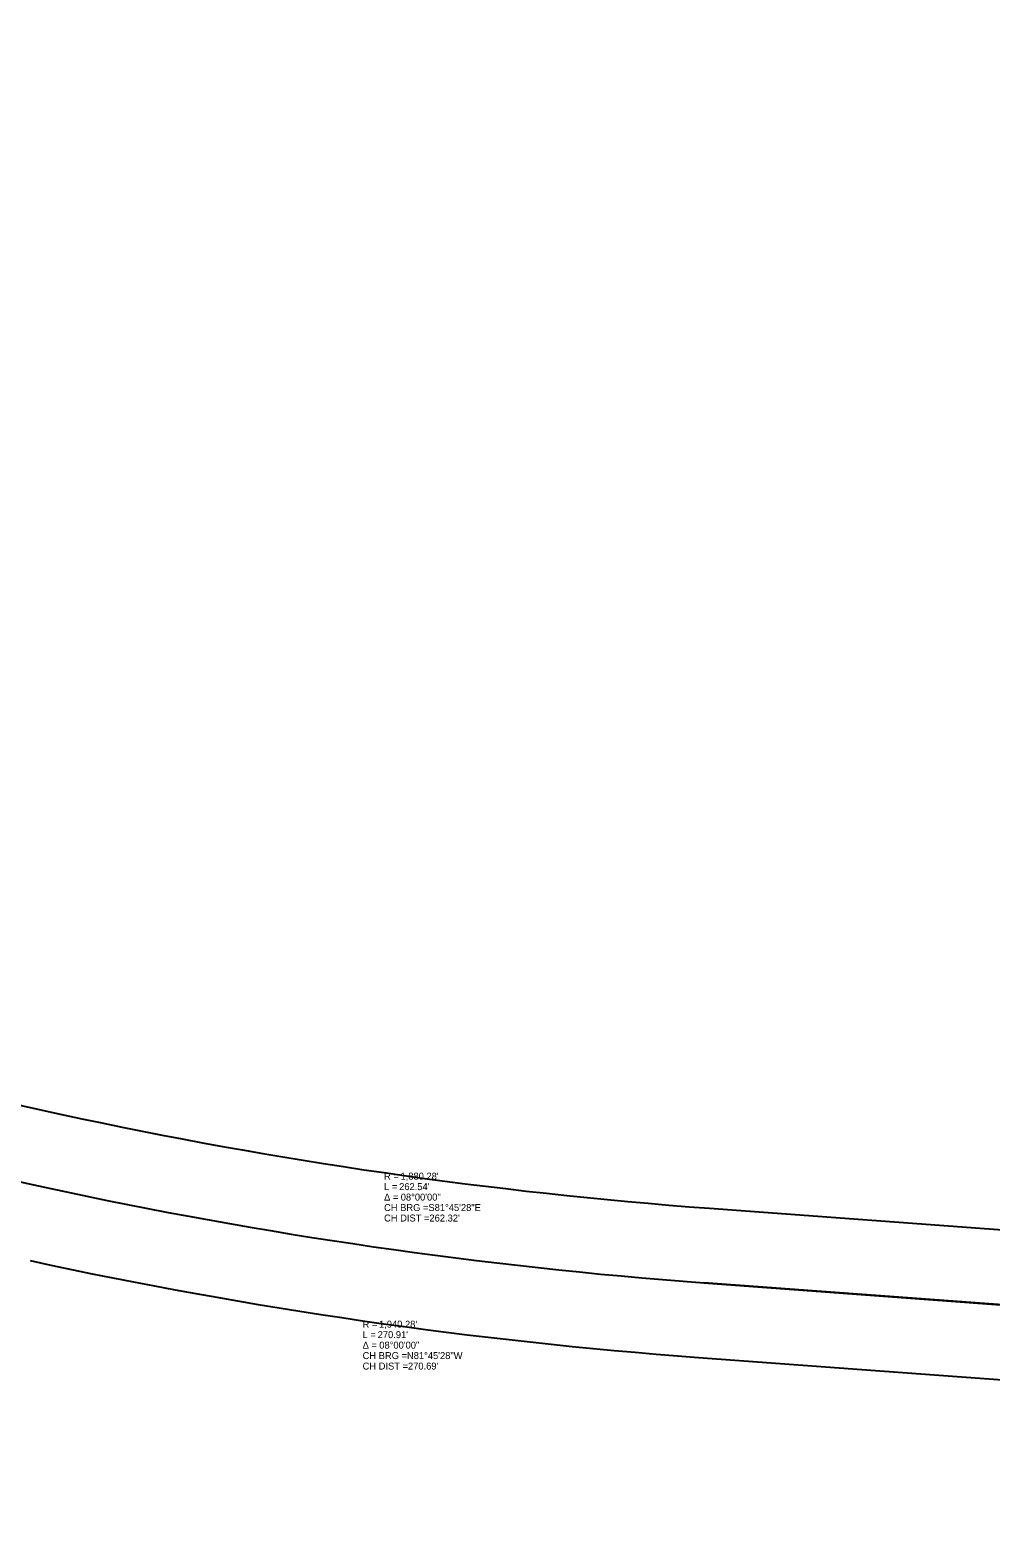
# Model space of a CAD drawing. Extents: x 2379325 to 2382869, y 256594 to 258871.
# Drawn here: x 2380645 to 2381031, y 257872 to 258477 of the extents above; entities that cross this region are included whole.
import ezdxf

# ---------------------------------------------------------------- set-up
doc = ezdxf.new("R2010")
doc.units = 0
for name, color, linetype in [('Default', 7, 'Continuous'), ('DR_P_Headwall', 7, 'Continuous'), ('PTS_PVMT', 7, 'Continuous'), ('SC_Scratch2', 7, 'Continuous')]:
    doc.layers.add(name, color=color, linetype=linetype)

msp = doc.modelspace()

# ---------------------------------------------------------------- linework, layer by layer
at = {"layer": 'DR_P_Headwall'}
for p, q in [((2380917.79, 258004.56), (2381895.07, 257932.07)), ((2380913.35, 257944.73), (2381889.15, 257872.35))]:
    msp.add_line(p, q, dxfattribs=at)
for centre, radius, start, end in [((2380955.55, 259412.67), 1402.39, 247.25233, 257.75788), ((2381056.88, 259879.69), 1880.28, 257.75788, 265.75788), ((2381056.88, 259879.69), 1940.28, 257.75788, 265.75788)]:
    msp.add_arc(centre, radius, start, end, dxfattribs=at)
at = {"layer": 'PTS_PVMT'}
for points in [[(2380915.57, 257974.64), (2381892.11, 257902.21), (2381953.3, 257894.61), (2382069.47, 257890.07), (2382200.46, 257892.92), (2382282.14, 257907.78), (2382270.85, 258207.56), (2382395.58, 258240.12), (2382408.52, 258119.54), (2382529.94, 258163.94), (2382565.45, 257993.51), (2382716.17, 258049.69), (2382661.23, 258620.32), (2382184.82, 258609.93), (2381665.09, 258580.43), (2381008.69, 258600.49), (2380481.9, 258662.85), (2379503.04, 258870.93), (2379508.92, 258601.15), (2380163.69, 258211.64)], [(2381210.33, 257952.66), (2380915.57, 257974.64)]]:
    msp.add_lwpolyline(points, dxfattribs=at)
for centre, radius, start, end in [((2380955.55, 259412.67), 1432.39, 247.25233, 257.75788), ((2380955.55, 259412.67), 1432.39, 247.25233, 257.75788), ((2381056.88, 259879.69), 1910.28, 257.75788, 265.75788), ((2381056.88, 259879.69), 1910.28, 257.75788, 265.75788)]:
    msp.add_arc(centre, radius, start, end, dxfattribs=at)
at = {"layer": 'SC_Scratch2'}
msp.add_line((2381892.11, 257902.21), (2380915.57, 257974.64), dxfattribs=at)
for centre, radius, start, end in [((2380955.55, 259412.67), 1432.39, 247.25233, 257.75788), ((2381056.88, 259879.69), 1910.28, 257.75788, 265.75788)]:
    msp.add_arc(centre, radius, start, end, dxfattribs=at)

# ---------------------------------------------------------------- texts
at = {"layer": 'Default'}
for s, p in [('R = ', (2380787.33, 258016.03)), ("1,880.28'", (2380793.92, 258016.03)), ('Δ = ', (2380787.33, 258007.63)), ('L = ', (2380787.33, 258011.83)), ("262.54'", (2380793.37, 258011.83)), ('08°00\'00"', (2380794.01, 258007.63)), ('CH BRG = ', (2380787.33, 258003.43)), ('S81°45\'28"E', (2380805.11, 258003.43)), ('CH DIST = ', (2380787.33, 257999.23)), ("262.32'", (2380805.51, 257999.23)), ('R = ', (2380778.73, 257956.65)), ('L = ', (2380778.73, 257952.45)), ("270.91'", (2380784.77, 257952.45)), ("1,940.28'", (2380785.31, 257956.65)), ('Δ = ', (2380778.73, 257948.25)), ('08°00\'00"', (2380785.41, 257948.25)), ('CH BRG = ', (2380778.73, 257944.05)), ('N81°45\'28"W', (2380796.51, 257944.05)), ('CH DIST = ', (2380778.73, 257939.85)), ("270.69'", (2380796.91, 257939.85))]:
    msp.add_text(s, height=2.8, dxfattribs=at).set_placement(p)

doc.saveas('drawing.dxf')
